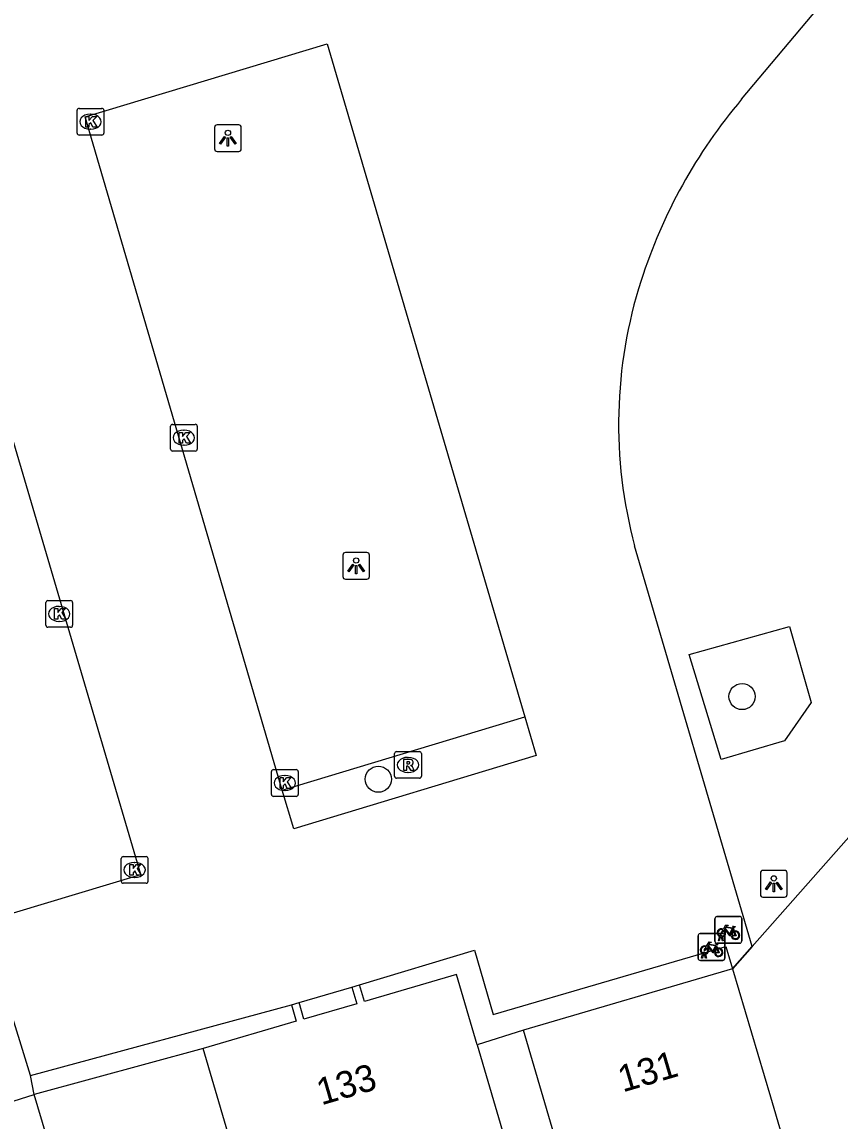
# Model space of a CAD drawing. Extents: x 159377 to 159983, y 382996 to 383595.
# Drawn here: x 159658.38 to 159688.99, y 383517.11 to 383558.26 of the extents above; entities that cross this region are included whole.
import ezdxf

# ---------------------------------------------------------------- set-up
doc = ezdxf.new("R2010")
doc.units = 0
for name, color, linetype in [('IMGEO_Boom', 7, 'Continuous'), ('IMGEO_Fietsenrek', 7, 'Continuous'), ('IMGEO_Kolk', 7, 'Continuous'), ('IMGEO_Lichtpunt', 7, 'Continuous'), ('IMGEO_Muur', 7, 'Continuous'), ('IMGEO_Pand', 7, 'Continuous'), ('IMGEO_Pand_nummerreeks', 7, 'Continuous'), ('IMGEO_Parkeervlak_open', 7, 'Continuous'), ('IMGEO_Rijbaan_lokaal_open', 7, 'Continuous'), ('IMGEO_Rioolput', 7, 'Continuous'), ('IMGEO_Voetpad_open', 7, 'Continuous')]:
    doc.layers.add(name, color=color, linetype=linetype)

msp = doc.modelspace()

# ---------------------------------------------------------------- linework, layer by layer
at = {"layer": 'IMGEO_Boom'}
for centre in [(159685.324, 383533.028), (159671.715, 383529.935)]:
    msp.add_circle(centre, 0.489, dxfattribs=at)
at = {"layer": 'IMGEO_Fietsenrek'}
for p, q in [((159684.386, 383524.801), (159685.227, 383524.801)), ((159685.227, 383524.801), (159684.386, 383524.801)), ((159684.311, 383523.876), (159684.311, 383524.717)), ((159684.311, 383524.717), (159684.311, 383523.876)), ((159684.998, 383524.35), (159685.034, 383524.255)), ((159685.311, 383524.726), (159685.311, 383523.885)), ((159685.311, 383523.885), (159685.311, 383524.726)), ((159683.679, 383523.234), (159683.679, 383524.075)), ((159683.679, 383524.075), (159683.679, 383523.234)), ((159683.754, 383524.159), (159684.595, 383524.159)), ((159684.595, 383524.159), (159683.754, 383524.159)), ((159684.438, 383523.885), (159684.477, 383524.045)), ((159684.507, 383524.033), (159684.472, 383523.885)), ((159684.549, 383524.057), (159684.548, 383524.061)), ((159684.59, 383523.885), (159684.556, 383524.027)), ((159684.58, 383524.068), (159684.581, 383524.061)), ((159684.588, 383524.031), (159684.623, 383523.885)), ((159684.679, 383524.084), (159684.679, 383523.243)), ((159684.679, 383523.243), (159684.679, 383524.084)), ((159684.366, 383523.708), (159684.402, 383523.613)), ((159685.236, 383523.801), (159684.395, 383523.801)), ((159684.395, 383523.801), (159685.236, 383523.801)), ((159684.472, 383523.885), (159684.438, 383523.885)), ((159684.623, 383523.885), (159684.59, 383523.885)), ((159684.604, 383523.159), (159683.763, 383523.159)), ((159683.763, 383523.159), (159684.604, 383523.159)), ((159683.806, 383523.243), (159683.845, 383523.403)), ((159683.84, 383523.243), (159683.806, 383523.243)), ((159683.875, 383523.391), (159683.84, 383523.243)), ((159683.917, 383523.415), (159683.916, 383523.419)), ((159683.958, 383523.243), (159683.924, 383523.385)), ((159683.948, 383523.426), (159683.949, 383523.419)), ((159683.956, 383523.389), (159683.991, 383523.243)), ((159683.991, 383523.243), (159683.958, 383523.243))]:
    msp.add_line(p, q, dxfattribs=at)
for points in [[(159684.624, 383524.327), (159684.719, 383524.491), (159684.805, 383524.477), (159684.807, 383524.468), (159684.751, 383524.457), (159684.724, 383524.412), (159684.98, 383524.371)], [(159684.92, 383524.083), (159684.87, 383524.083), (159684.679, 383524.334), (159684.66, 383524.302)], [(159684.967, 383524.346), (159684.71, 383524.387), (159684.693, 383524.358), (159684.86, 383524.138), (159684.967, 383524.346)], [(159684.98, 383524.371), (159685.005, 383524.42), (159684.999, 383524.424), (159684.976, 383524.428), (159684.964, 383524.435), (159684.963, 383524.438), (159684.965, 383524.443), (159685.06, 383524.428), (159685.062, 383524.418), (159685.052, 383524.405), (159685.04, 383524.399), (159685.026, 383524.405), (159684.998, 383524.35)], [(159684.645, 383524.275), (159684.593, 383524.185), (159684.553, 383524.16), (159684.554, 383524.207), (159684.609, 383524.301)], [(159685.015, 383524.248), (159684.985, 383524.325), (159684.876, 383524.107), (159684.919, 383524.107)], [(159684.949, 383524.107), (159685.069, 383524.106), (159685.025, 383524.22)], [(159685.045, 383524.227), (159685.1, 383524.082), (159684.95, 383524.082)], [(159684.013, 383523.633), (159683.961, 383523.543), (159683.921, 383523.518), (159683.922, 383523.565), (159683.977, 383523.659)], [(159683.992, 383523.685), (159684.087, 383523.849), (159684.173, 383523.835), (159684.175, 383523.826), (159684.119, 383523.815), (159684.092, 383523.77), (159684.348, 383523.729)], [(159684.288, 383523.441), (159684.238, 383523.441), (159684.047, 383523.692), (159684.028, 383523.66)], [(159684.335, 383523.704), (159684.078, 383523.745), (159684.061, 383523.716), (159684.228, 383523.496), (159684.335, 383523.704)], [(159684.383, 383523.606), (159684.353, 383523.683), (159684.244, 383523.465), (159684.287, 383523.465)], [(159684.317, 383523.465), (159684.437, 383523.464), (159684.393, 383523.578)], [(159684.413, 383523.585), (159684.468, 383523.44), (159684.318, 383523.44)], [(159684.348, 383523.729), (159684.373, 383523.778), (159684.367, 383523.782), (159684.344, 383523.786), (159684.332, 383523.793), (159684.331, 383523.796), (159684.333, 383523.801), (159684.428, 383523.786), (159684.43, 383523.776), (159684.42, 383523.763), (159684.408, 383523.757), (159684.394, 383523.763), (159684.366, 383523.708)]]:
    msp.add_lwpolyline(points, dxfattribs=at)
for centre, radius, start, end in [((159684.389, 383524.723), 0.0779, 92.4484, 184.2845), ((159684.389, 383524.723), 0.0779, 92.4484, 184.2845), ((159685.233, 383524.723), 0.0779, 2.4484, 94.2845), ((159685.233, 383524.723), 0.0779, 2.4484, 94.2845), ((159684.551, 383524.186), 0.159, 62.6766, 242.1369), ((159683.757, 383524.081), 0.0779, 92.4484, 184.2845), ((159683.757, 383524.081), 0.0779, 92.4484, 184.2845), ((159684.551, 383524.186), 0.129, 63.3192, 238.903), ((159684.531, 383524.057), 0.0499, 12.8025, 158.6934), ((159684.551, 383524.186), 0.159, 253.9967, 271.7867), ((159684.531, 383524.057), 0.0174, 12.8025, 163.4502), ((159684.551, 383524.186), 0.129, 253.415, 269.0204), ((159684.551, 383524.186), 0.129, 283.6043, 43.4302), ((159684.551, 383524.186), 0.159, 283.5766, 46.6042), ((159684.601, 383524.081), 0.0779, 2.4484, 94.2845), ((159684.601, 383524.081), 0.0779, 2.4484, 94.2845), ((159685.078, 383524.102), 0.159, 113.3408, 178.3217), ((159685.078, 383524.102), 0.159, 187.0065, 105.7708), ((159685.078, 383524.102), 0.129, 113.923, 177.9556), ((159685.078, 383524.102), 0.129, 188.6715, 104.5883), ((159683.919, 383523.544), 0.159, 62.6766, 242.1369), ((159683.919, 383523.544), 0.129, 63.3192, 238.903), ((159683.919, 383523.544), 0.129, 283.6043, 43.4302), ((159683.919, 383523.544), 0.159, 283.5766, 46.6042), ((159684.446, 383523.46), 0.159, 113.3408, 178.3217), ((159684.446, 383523.46), 0.159, 187.0065, 105.7708), ((159684.389, 383523.879), 0.0779, 182.4484, 274.2845), ((159684.389, 383523.879), 0.0779, 182.4484, 274.2845), ((159684.446, 383523.46), 0.129, 113.923, 177.9556), ((159684.446, 383523.46), 0.129, 188.6715, 104.5883), ((159685.233, 383523.879), 0.0779, 272.4484, 4.2845), ((159685.233, 383523.879), 0.0779, 272.4484, 4.2845), ((159683.757, 383523.237), 0.0779, 182.4484, 274.2845), ((159683.757, 383523.237), 0.0779, 182.4484, 274.2845), ((159683.899, 383523.415), 0.0499, 12.8025, 158.6934), ((159683.919, 383523.544), 0.159, 253.9967, 271.7867), ((159683.899, 383523.415), 0.0174, 12.8025, 163.4502), ((159683.919, 383523.544), 0.129, 253.415, 269.0204), ((159684.601, 383523.237), 0.0779, 272.4484, 4.2845), ((159684.601, 383523.237), 0.0779, 272.4484, 4.2845)]:
    msp.add_arc(centre, radius, start, end, dxfattribs=at)
at = {"layer": 'IMGEO_Kolk'}
for p, q in [((159660.445, 383554.104), (159660.445, 383554.956)), ((159660.52, 383555.03), (159661.372, 383555.03)), ((159660.933, 383554.81), (159660.958, 383554.81)), ((159661.446, 383554.956), (159661.446, 383554.104)), ((159661.372, 383554.03), (159660.52, 383554.03)), ((159660.956, 383554.25), (159660.931, 383554.25)), ((159663.94, 383542.284), (159663.94, 383543.136)), ((159664.015, 383543.21), (159664.867, 383543.21)), ((159664.428, 383542.99), (159664.453, 383542.99)), ((159664.941, 383543.136), (159664.941, 383542.284)), ((159664.451, 383542.43), (159664.426, 383542.43)), ((159664.867, 383542.21), (159664.015, 383542.21)), ((159659.276, 383535.694), (159659.276, 383536.546)), ((159659.351, 383536.62), (159660.203, 383536.62)), ((159659.764, 383536.4), (159659.789, 383536.4)), ((159660.277, 383536.546), (159660.277, 383535.694)), ((159660.203, 383535.62), (159659.351, 383535.62)), ((159659.787, 383535.84), (159659.762, 383535.84)), ((159667.716, 383529.368), (159667.716, 383530.22)), ((159667.791, 383530.294), (159668.643, 383530.294)), ((159668.717, 383530.22), (159668.717, 383529.368)), ((159668.204, 383530.074), (159668.229, 383530.074)), ((159668.643, 383529.294), (159667.791, 383529.294)), ((159668.227, 383529.514), (159668.202, 383529.514)), ((159662.096, 383526.117), (159662.096, 383526.969)), ((159662.171, 383527.043), (159663.023, 383527.043)), ((159662.584, 383526.823), (159662.609, 383526.823)), ((159663.097, 383526.969), (159663.097, 383526.117)), ((159663.023, 383526.043), (159662.171, 383526.043)), ((159662.607, 383526.263), (159662.582, 383526.263))]:
    msp.add_line(p, q, dxfattribs=at)
for points in [[(159660.445, 383554.104), (159660.445, 383554.956)], [(159660.52, 383555.03), (159661.372, 383555.03)], [(159661.446, 383554.956), (159661.446, 383554.104)], [(159660.766, 383554.73), (159660.889, 383554.73), (159660.889, 383554.579), (159661.019, 383554.73), (159661.183, 383554.73), (159661.037, 383554.579), (159661.19, 383554.33), (159661.038, 383554.33), (159660.953, 383554.494), (159660.889, 383554.427), (159660.889, 383554.33), (159660.766, 383554.33), (159660.766, 383554.73)], [(159661.372, 383554.03), (159660.52, 383554.03)], [(159663.94, 383542.284), (159663.94, 383543.136)], [(159664.015, 383543.21), (159664.867, 383543.21)], [(159664.261, 383542.91), (159664.384, 383542.91), (159664.384, 383542.759), (159664.514, 383542.91), (159664.678, 383542.91), (159664.532, 383542.759), (159664.685, 383542.51), (159664.533, 383542.51), (159664.448, 383542.674), (159664.384, 383542.607), (159664.384, 383542.51), (159664.261, 383542.51), (159664.261, 383542.91)], [(159664.941, 383543.136), (159664.941, 383542.284)], [(159664.867, 383542.21), (159664.015, 383542.21)], [(159659.276, 383535.694), (159659.276, 383536.546)], [(159659.351, 383536.62), (159660.203, 383536.62)], [(159659.597, 383536.32), (159659.72, 383536.32), (159659.72, 383536.169), (159659.85, 383536.32), (159660.014, 383536.32), (159659.868, 383536.169), (159660.021, 383535.92), (159659.869, 383535.92), (159659.784, 383536.084), (159659.72, 383536.017), (159659.72, 383535.92), (159659.597, 383535.92), (159659.597, 383536.32)], [(159660.277, 383536.546), (159660.277, 383535.694)], [(159660.203, 383535.62), (159659.351, 383535.62)], [(159667.716, 383529.368), (159667.716, 383530.22)], [(159667.791, 383530.294), (159668.643, 383530.294)], [(159668.717, 383530.22), (159668.717, 383529.368)], [(159668.037, 383529.994), (159668.16, 383529.994), (159668.16, 383529.843), (159668.29, 383529.994), (159668.454, 383529.994), (159668.308, 383529.843), (159668.461, 383529.594), (159668.309, 383529.594), (159668.224, 383529.758), (159668.16, 383529.691), (159668.16, 383529.594), (159668.037, 383529.594), (159668.037, 383529.994)], [(159668.643, 383529.294), (159667.791, 383529.294)], [(159662.096, 383526.117), (159662.096, 383526.969)], [(159662.171, 383527.043), (159663.023, 383527.043)], [(159663.097, 383526.969), (159663.097, 383526.117)], [(159662.417, 383526.743), (159662.54, 383526.743), (159662.54, 383526.592), (159662.67, 383526.743), (159662.834, 383526.743), (159662.688, 383526.592), (159662.841, 383526.343), (159662.689, 383526.343), (159662.604, 383526.507), (159662.54, 383526.44), (159662.54, 383526.343), (159662.417, 383526.343), (159662.417, 383526.743)], [(159663.023, 383526.043), (159662.171, 383526.043)]]:
    msp.add_lwpolyline(points, dxfattribs=at)
for centre, start, end in [((159660.522, 383554.954), 91.552, 178.448), ((159660.522, 383554.954), 91.552, 178.448), ((159661.37, 383554.954), 1.552, 88.448), ((159661.37, 383554.954), 1.552, 88.448), ((159660.522, 383554.106), 181.552, 268.448), ((159660.522, 383554.106), 181.552, 268.448), ((159661.37, 383554.106), 271.552, 358.448), ((159661.37, 383554.106), 271.552, 358.448), ((159664.017, 383543.134), 91.552, 178.448), ((159664.017, 383543.134), 91.552, 178.448), ((159664.865, 383543.134), 1.552, 88.448), ((159664.865, 383543.134), 1.552, 88.448), ((159664.017, 383542.286), 181.552, 268.448), ((159664.017, 383542.286), 181.552, 268.448), ((159664.865, 383542.286), 271.552, 358.448), ((159664.865, 383542.286), 271.552, 358.448), ((159659.353, 383536.544), 91.552, 178.448), ((159659.353, 383536.544), 91.552, 178.448), ((159660.201, 383536.544), 1.552, 88.448), ((159660.201, 383536.544), 1.552, 88.448), ((159659.353, 383535.696), 181.552, 268.448), ((159659.353, 383535.696), 181.552, 268.448), ((159660.201, 383535.696), 271.552, 358.448), ((159660.201, 383535.696), 271.552, 358.448), ((159667.793, 383530.218), 91.552, 178.448), ((159667.793, 383530.218), 91.552, 178.448), ((159668.641, 383530.218), 1.552, 88.448), ((159668.641, 383530.218), 1.552, 88.448), ((159667.793, 383529.37), 181.552, 268.448), ((159667.793, 383529.37), 181.552, 268.448), ((159668.641, 383529.37), 271.552, 358.448), ((159668.641, 383529.37), 271.552, 358.448), ((159662.173, 383526.967), 91.552, 178.448), ((159662.173, 383526.967), 91.552, 178.448), ((159663.021, 383526.967), 1.552, 88.448), ((159663.021, 383526.967), 1.552, 88.448), ((159662.173, 383526.119), 181.552, 268.448), ((159662.173, 383526.119), 181.552, 268.448), ((159663.021, 383526.119), 271.552, 358.448), ((159663.021, 383526.119), 271.552, 358.448)]:
    msp.add_arc(centre, 0.0765, start, end, dxfattribs=at)
for centre, major_axis, ratio, start_param, end_param in [((159660.932, 383554.53), (-0.387, 0.002), 0.722429, 4.712389, 7.853982), ((159660.957, 383554.53), (-0.39, 0.002), 0.717154, 1.570796, 4.712389), ((159664.427, 383542.71), (-0.387, 0.002), 0.722429, 4.712389, 7.853982), ((159664.452, 383542.71), (-0.39, 0.002), 0.717154, 1.570796, 4.712389), ((159659.763, 383536.12), (-0.387, 0.002), 0.722429, 4.712389, 7.853982), ((159659.788, 383536.12), (-0.39, 0.002), 0.717154, 1.570796, 4.712389), ((159668.203, 383529.794), (-0.387, 0.002), 0.722429, 4.712389, 7.853982), ((159668.228, 383529.794), (-0.39, 0.002), 0.717154, 1.570796, 4.712389), ((159662.583, 383526.543), (-0.387, 0.002), 0.722429, 4.712389, 7.853982), ((159662.608, 383526.543), (-0.39, 0.002), 0.717154, 1.570796, 4.712389)]:
    msp.add_ellipse(centre, major_axis=major_axis, ratio=ratio, start_param=start_param, end_param=end_param, dxfattribs=at)
at = {"layer": 'IMGEO_Lichtpunt'}
for p, q in [((159666.49, 383554.412), (159665.682, 383554.412)), ((159666.49, 383554.412), (159665.682, 383554.412)), ((159665.588, 383554.317), (159665.588, 383553.51)), ((159665.588, 383554.317), (159665.588, 383553.51)), ((159666.584, 383553.51), (159666.584, 383554.317)), ((159666.584, 383553.51), (159666.584, 383554.317)), ((159665.682, 383553.416), (159666.49, 383553.416)), ((159665.682, 383553.416), (159666.49, 383553.416)), ((159670.387, 383538.32), (159670.387, 383537.513)), ((159670.387, 383538.32), (159670.387, 383537.513)), ((159671.289, 383538.415), (159670.481, 383538.415)), ((159671.289, 383538.415), (159670.481, 383538.415)), ((159671.383, 383537.513), (159671.383, 383538.32)), ((159671.383, 383537.513), (159671.383, 383538.32)), ((159670.481, 383537.419), (159671.289, 383537.419)), ((159670.481, 383537.419), (159671.289, 383537.419)), ((159686.012, 383526.428), (159686.012, 383525.621)), ((159686.012, 383526.428), (159686.012, 383525.621)), ((159686.914, 383526.523), (159686.106, 383526.523)), ((159686.914, 383526.523), (159686.106, 383526.523)), ((159687.008, 383525.621), (159687.008, 383526.428)), ((159687.008, 383525.621), (159687.008, 383526.428)), ((159686.106, 383525.527), (159686.914, 383525.527)), ((159686.106, 383525.527), (159686.914, 383525.527))]:
    msp.add_line(p, q, dxfattribs=at)
for points in [[(159665.962, 383553.981), (159666.001, 383553.953), (159665.813, 383553.691), (159665.775, 383553.718), (159665.962, 383553.981)], [(159666.174, 383553.953), (159666.212, 383553.98), (159666.399, 383553.718), (159666.36, 383553.69), (159666.174, 383553.953)], [(159666.064, 383553.933), (159666.111, 383553.933), (159666.111, 383553.611), (159666.064, 383553.611), (159666.064, 383553.933)], [(159670.761, 383537.984), (159670.8, 383537.956), (159670.612, 383537.694), (159670.574, 383537.721), (159670.761, 383537.984)], [(159670.863, 383537.936), (159670.91, 383537.936), (159670.91, 383537.614), (159670.863, 383537.614), (159670.863, 383537.936)], [(159670.973, 383537.956), (159671.011, 383537.983), (159671.198, 383537.721), (159671.159, 383537.693), (159670.973, 383537.956)], [(159686.386, 383526.092), (159686.425, 383526.064), (159686.237, 383525.802), (159686.199, 383525.829), (159686.386, 383526.092)], [(159686.488, 383526.044), (159686.535, 383526.044), (159686.535, 383525.722), (159686.488, 383525.722), (159686.488, 383526.044)], [(159686.598, 383526.064), (159686.636, 383526.091), (159686.823, 383525.829), (159686.784, 383525.801), (159686.598, 383526.064)]]:
    msp.add_lwpolyline(points, dxfattribs=at)
for centre in [(159666.087, 383554.115), (159670.886, 383538.118), (159686.511, 383526.226)]:
    msp.add_circle(centre, 0.0994, dxfattribs=at)
for centre, start, end in [((159665.682, 383554.317), 90, 180), ((159665.682, 383554.317), 90, 180), ((159666.49, 383554.317), 0, 90), ((159666.49, 383554.317), 0, 90), ((159665.682, 383553.51), 180, 270), ((159665.682, 383553.51), 180, 270), ((159666.49, 383553.51), 270, 0), ((159666.49, 383553.51), 270, 360), ((159670.481, 383538.32), 90, 180), ((159670.481, 383538.32), 90, 180), ((159671.289, 383538.32), 0, 90), ((159671.289, 383538.32), 0, 90), ((159670.481, 383537.513), 180, 270), ((159670.481, 383537.513), 180, 270), ((159671.289, 383537.513), 270, 0), ((159671.289, 383537.513), 270, 360), ((159686.106, 383526.428), 90, 180), ((159686.106, 383526.428), 90, 180), ((159686.914, 383526.428), 0, 90), ((159686.914, 383526.428), 0, 90), ((159686.106, 383525.621), 180, 270), ((159686.106, 383525.621), 180, 270), ((159686.914, 383525.621), 270, 0), ((159686.914, 383525.621), 270, 360)]:
    msp.add_arc(centre, 0.0946, start, end, dxfattribs=at)
at = {"layer": 'IMGEO_Muur'}
for points in [[(159685.704, 383523.677), (159691.309, 383530.03), (159691.441, 383530.17)], [(159684.971, 383522.846), (159685.704, 383523.677)]]:
    msp.add_lwpolyline(points, dxfattribs=at)
at = {"layer": 'IMGEO_Pand'}
for points in [[(159684.971, 383522.846), (159686.382, 383518.05), (159688.93, 383509.391), (159686.052, 383508.544), (159685.091, 383511.813), (159684.878, 383511.751), (159684.289, 383513.754), (159679.555, 383512.361), (159678.559, 383515.749), (159677.148, 383520.545)], [(159684.971, 383522.846), (159677.148, 383520.545)], [(159675.415, 383519.995), (159674.64, 383522.628), (159671.198, 383521.616), (159671.014, 383522.247)], [(159670.726, 383522.163), (159670.908, 383521.539), (159668.931, 383520.961), (159668.749, 383521.585)], [(159670.726, 383522.163), (159671.014, 383522.247)], [(159668.461, 383521.501), (159668.641, 383520.883), (159665.158, 383519.859)], [(159668.461, 383521.501), (159668.749, 383521.585)], [(159669.403, 383505.431), (159665.158, 383519.859)], [(159675.415, 383519.995), (159676.826, 383515.199)]]:
    msp.add_lwpolyline(points, dxfattribs=at)
at = {"layer": 'IMGEO_Parkeervlak_open'}
msp.add_lwpolyline([(159668.114, 383529.524), (159677.202, 383532.269)], dxfattribs=at)
at = {"layer": 'IMGEO_Rijbaan_lokaal_open'}
for points in [[(159685.304, 383555.367), (159691.975, 383563.321)], [(159668.114, 383529.524), (159660.746, 383554.717), (159669.8, 383557.445), (159677.202, 383532.269)], [(159658.059, 383524.939), (159662.824, 383526.367), (159653.793, 383557.052), (159649.066, 383555.642)], [(159685.704, 383523.677), (159681.304, 383538.663)], [(159677.202, 383532.269), (159677.615, 383530.825), (159668.551, 383528.08), (159668.114, 383529.524)], [(159658.706, 383518.849), (159656.913, 383524.598)], [(159671.014, 383522.247), (159675.313, 383523.537), (159676.016, 383521.133), (159684.721, 383523.682), (159684.971, 383522.846)], [(159685.704, 383523.677), (159684.971, 383522.846)], [(159668.749, 383521.585), (159670.726, 383522.163)], [(159658.706, 383518.849), (159668.461, 383521.501)]]:
    msp.add_lwpolyline(points, dxfattribs=at)
for centre, radius, start, end in [((159700.52, 383542.503), 19.925, 139.7869, 162.223), ((159698.257, 383543.214), 17.553, 162.1795, 195.0264)]:
    msp.add_arc(centre, radius, start, end, dxfattribs=at)
at = {"layer": 'IMGEO_Rioolput'}
for p, q in [((159672.399, 383530.972), (159673.251, 383530.972)), ((159672.324, 383530.046), (159672.324, 383530.898)), ((159672.812, 383530.752), (159672.837, 383530.752)), ((159673.325, 383530.898), (159673.325, 383530.046)), ((159672.835, 383530.192), (159672.81, 383530.192)), ((159673.251, 383529.972), (159672.399, 383529.972))]:
    msp.add_line(p, q, dxfattribs=at)
for points in [[(159672.399, 383530.972), (159673.251, 383530.972)], [(159672.324, 383530.046), (159672.324, 383530.898)], [(159672.913, 383530.67), (159672.661, 383530.672), (159672.661, 383530.272)], [(159672.839, 383530.591), (159672.785, 383530.591), (159672.785, 383530.51)], [(159672.785, 383530.51), (159672.837, 383530.51)], [(159673.325, 383530.898), (159673.325, 383530.046)], [(159672.661, 383530.272), (159672.785, 383530.272), (159672.785, 383530.434), (159672.796, 383530.434)], [(159672.843, 383530.405), (159672.914, 383530.272), (159673.054, 383530.272), (159672.989, 383530.398)], [(159673.251, 383529.972), (159672.399, 383529.972)]]:
    msp.add_lwpolyline(points, dxfattribs=at)
for centre, radius, start, end in [((159672.401, 383530.896), 0.0765, 91.552, 178.448), ((159672.401, 383530.896), 0.0765, 91.552, 178.448), ((159673.249, 383530.896), 0.0765, 1.552, 88.448), ((159673.249, 383530.896), 0.0765, 1.552, 88.448), ((159672.821, 383530.699), 0.19, 274.7715, 282.9687), ((159672.845, 383530.495), 0.0964, 77.0061, 93.1865), ((159672.859, 383530.552), 0.0378, 276.6634, 79.6772), ((159672.912, 383530.56), 0.109, 350.3612, 89.416), ((159672.91, 383530.56), 0.112, 277.5842, 350.9817), ((159672.795, 383530.381), 0.0533, 26.0293, 88.6989), ((159672.894, 383530.345), 0.108, 29.5134, 73.7905), ((159672.401, 383530.048), 0.0765, 181.552, 268.448), ((159672.401, 383530.048), 0.0765, 181.552, 268.448), ((159673.249, 383530.048), 0.0765, 271.552, 358.448), ((159673.249, 383530.048), 0.0765, 271.552, 358.448)]:
    msp.add_arc(centre, radius, start, end, dxfattribs=at)
for centre, major_axis, ratio, start_param, end_param in [((159672.811, 383530.472), (-0.387, 0.002), 0.722429, 4.712389, 7.853982), ((159672.836, 383530.472), (-0.39, 0.002), 0.717154, 1.570796, 4.712389)]:
    msp.add_ellipse(centre, major_axis=major_axis, ratio=ratio, start_param=start_param, end_param=end_param, dxfattribs=at)
at = {"layer": 'IMGEO_Voetpad_open'}
for points in [[(159684.536, 383530.675), (159683.345, 383534.599), (159687.094, 383535.652), (159687.909, 383532.805), (159686.911, 383531.375), (159684.536, 383530.675)], [(159691.441, 383530.17), (159691.309, 383530.03), (159685.704, 383523.677)], [(159677.148, 383520.545), (159675.415, 383519.995)], [(159665.158, 383519.859), (159658.841, 383518.144)], [(159658.841, 383518.144), (159658.706, 383518.849)], [(159655.715, 383517.153), (159658.841, 383518.144)], [(159695.793, 383386.432), (159689.89, 383408.493), (159681.184, 383441.029), (159670.697, 383478.285), (159669.551, 383482.179), (159664.244, 383500), (159658.841, 383518.144)]]:
    msp.add_lwpolyline(points, dxfattribs=at)

# ---------------------------------------------------------------- texts
at = {"layer": 'IMGEO_Pand_nummerreeks'}
for s, rotation, p in [('131', 16.3903, (159680.86, 383518.217)), ('133', 16.2777, (159669.583, 383517.734))]:
    msp.add_text(s, height=1, rotation=rotation, dxfattribs=at).set_placement(p)

doc.saveas('drawing.dxf')
